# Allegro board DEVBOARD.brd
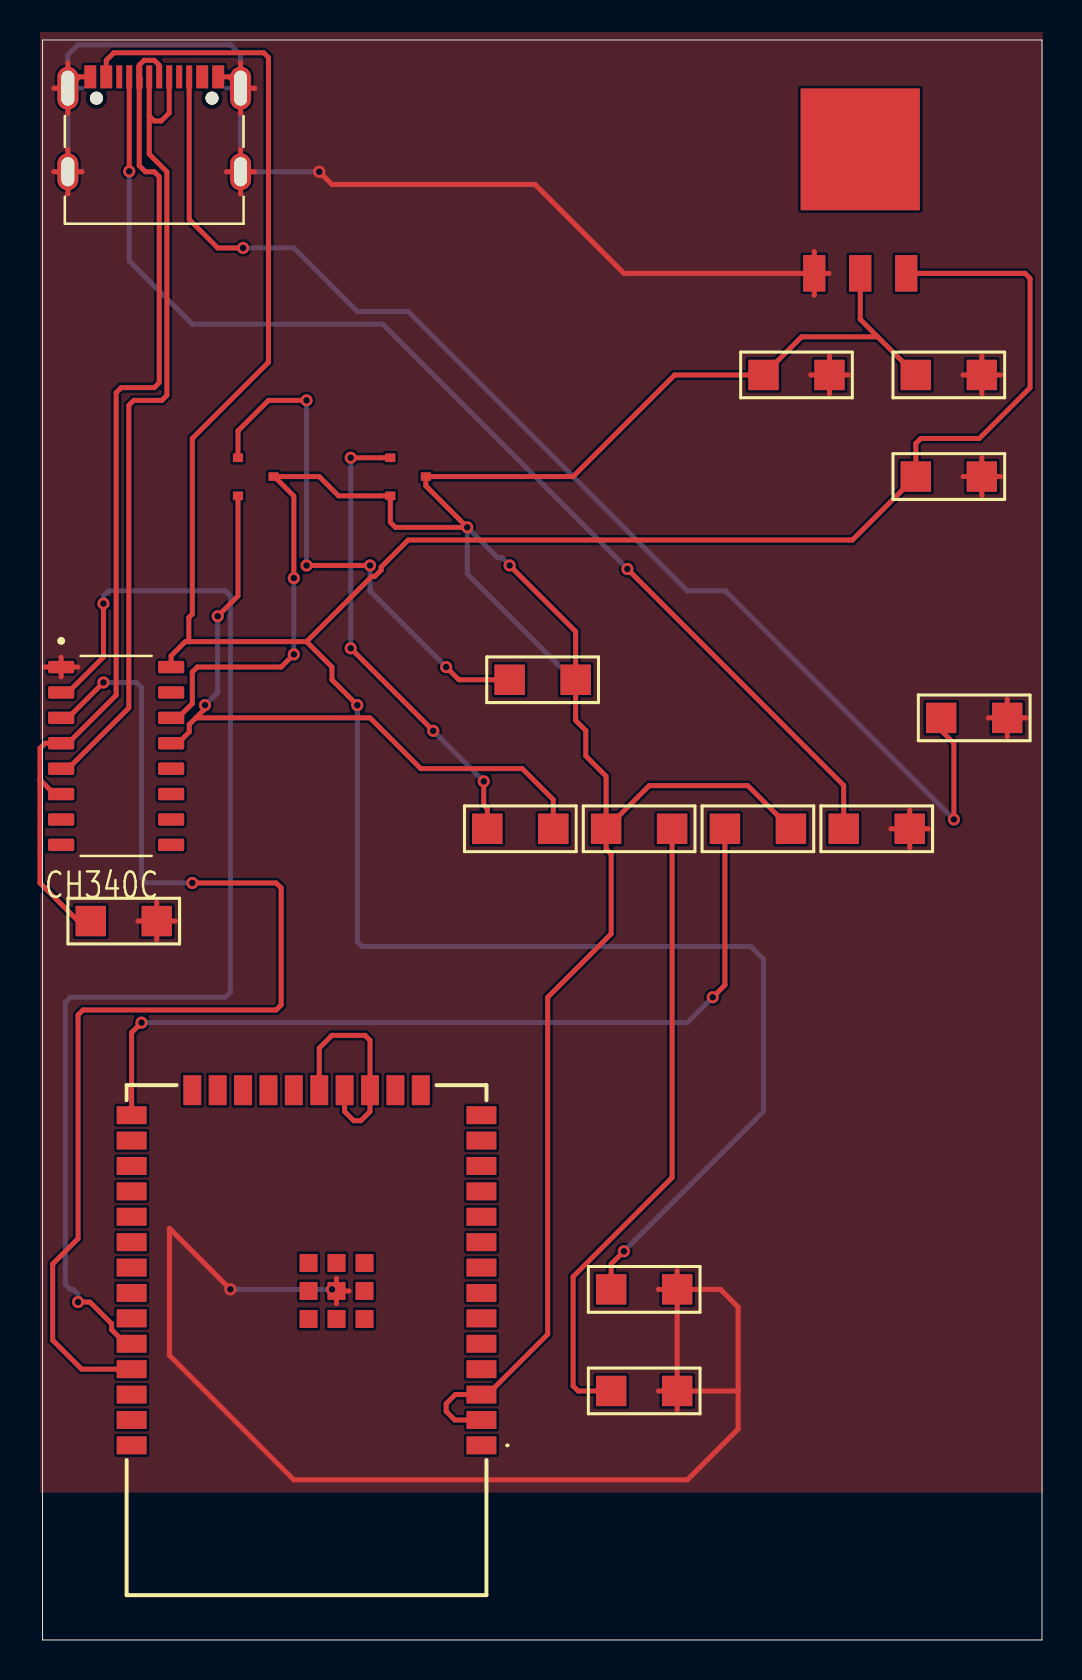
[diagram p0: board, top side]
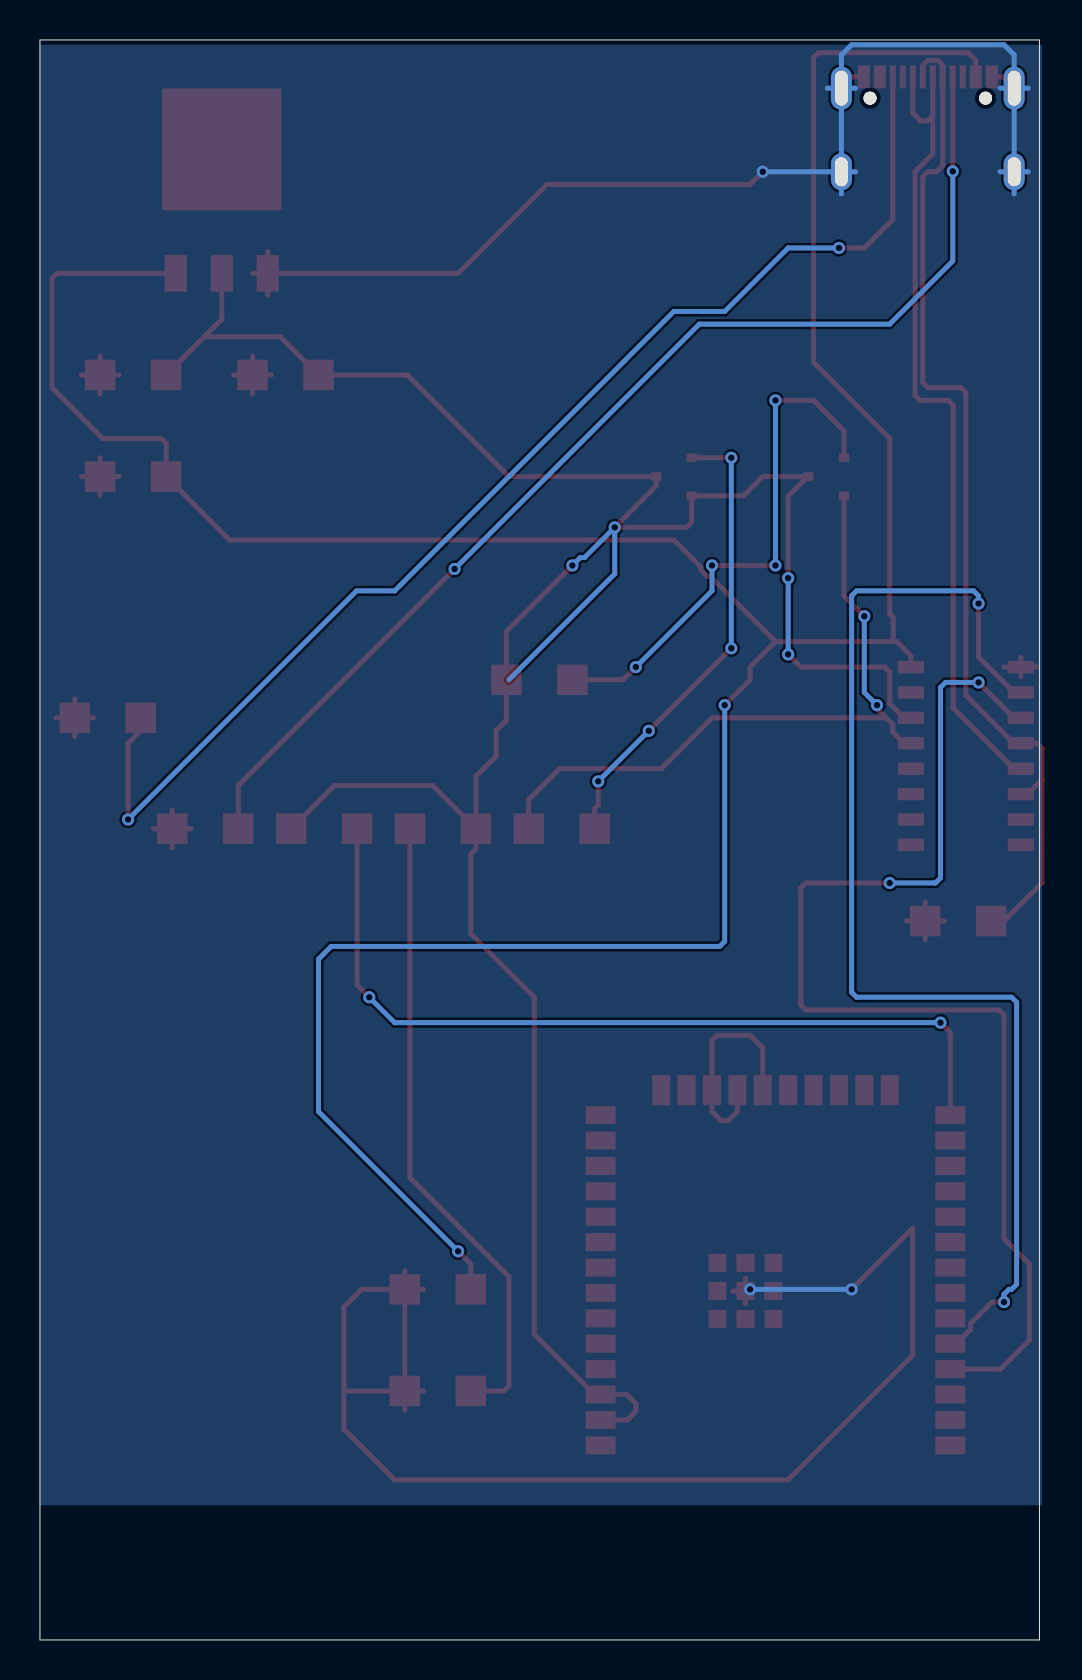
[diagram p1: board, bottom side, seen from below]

Outline 50 x 80 mm; copper layers: TOP, BOTTOM. Coordinates in mm from the lower left corner of the outline.
Outline path: 0,80 50,80 50,0 0,0 0,80

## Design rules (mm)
constraint set DEFAULT: min track width 0.25

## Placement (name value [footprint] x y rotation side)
C3  10u  [SMC1206]  43.69 63.25 0 top
C4  100u  [SMC1206]  36.07 63.25 0 top
C5  100n  [SMC1206]  2.41 35.95 0 top
C6  10u  [SMC1206]  43.69 58.17 0 top
C7  100u  [SMC1206]  28.45 17.53 0 top
C8  1u  [SMC1206]  28.45 12.45 0 top
IC1  ESP32-WROOM-32E-N8  [ESP32WROOM32EN8]  13.21 14.99 180 top
J1  10155435-00011LF  [AMPHENOL_10155435-00031LF]  5.59 73.41 0 top
Q1  NPN  [SOT23]  10.67 58.17 0 top
Q2  NPN  [SOT23]  18.29 58.17 0 top
R1  10k  [SMC1206]  23.37 48.01 0 top
R2  10k  [SMC1206]  22.25 40.56 0 top
R3  5.1k  [SMC1206]  40.08 40.56 0 top
R4  5.1k  [SMC1206]  44.96 46.11 0 top
R5  10k  [SMC1206]  28.19 40.56 0 top
R6  10k  [SMC1206]  34.14 40.56 0 top
U1  AMS1117-33  [AMS1117]  38.61 68.33 0 top
U2  CH340C  [SOIC127P600X180-16N-1]  3.68 44.2 0 top

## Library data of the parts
C3-C7 = CAP
C8 = C
IC1 = ESP32-WROOM-32E-N8
J1 = 10155435-00011LF
Q1 Q2 = NPN
R1-R6 = R
U1 = AMS1117-33
U2 = CH340C

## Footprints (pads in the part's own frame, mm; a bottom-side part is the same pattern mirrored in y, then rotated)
AMPHENOL_10155435-00031LF
  round 0.65 hole 0.65 unplated: (-2.89,3.68) (2.89,3.68)
  rect 0.6x1.15 smd: A1_B12(-3.2,4.745) A4_B9(-2.4,4.745) B1_A12(3.2,4.745) B4_A9(2.4,4.745)
  rect 0.3x1.15 smd: A5(-1.25,4.745) A6(-0.25,4.745) A7(0.25,4.745) A8(1.25,4.745) B5(1.75,4.745) B6(0.75,4.745) B7(-0.75,4.745) B8(-1.75,4.745)
  oval 1.05x2.15 hole 0.65x1.75: SH1(-4.32,4.18) SH2(4.32,4.18)
  oval 1.05x1.85 hole 0.65x1.45: SH3(-4.32,0) SH4(4.32,0)
AMS1117
  rect 1.118x1.829 smd: 1(0,0) 2(2.3,0) 3(4.6,0)
  rect 5.969x6.096 smd: 4(2.3,6.2)
ESP32WROOM32EN8
  rect 1.5x0.9 smd: 1(-8.75,5.26) 2(-8.75,3.99) 3(-8.75,2.72) 4(-8.75,1.45) 5(-8.75,0.18) 6(-8.75,-1.09) 7(-8.75,-2.36) 8(-8.75,-3.63) 9(-8.75,-4.9) 10(-8.75,-6.17) 11(-8.75,-7.44) 12(-8.75,-8.71) 13(-8.75,-9.98) 14(-8.75,-11.25) 25(8.75,-11.25) 26(8.75,-9.98) 27(8.75,-8.71) 28(8.75,-7.44) 29(8.75,-6.17) 30(8.75,-4.9) 31(8.75,-3.63) 32(8.75,-2.36) 33(8.75,-1.09) 34(8.75,0.18) 35(8.75,1.45) 36(8.75,2.72) 37(8.75,3.99) 38(8.75,5.26)
  rect 0.9x1.5 smd: 15(-5.715,-12.5) 16(-4.445,-12.5) 17(-3.175,-12.5) 18(-1.905,-12.5) 19(-0.635,-12.5) 20(0.635,-12.5) 21(1.905,-12.5) 22(3.175,-12.5) 23(4.445,-12.5) 24(5.715,-12.5)
  rect 0.9x0.9 smd: 39(-2.9,-1.06) 40(-2.9,-2.46) 41(-2.9,-3.86) 42(-1.5,-3.86) 43(-0.1,-3.86) 44(-0.1,-2.46) 45(-0.1,-1.06) 46(-1.5,-1.06) 47(-1.5,-2.46)
SMC1206
  rect 1.524x1.524 smd: 1(0,0) 2(3.302,0)
SOIC127P600X180-16N-1
  custom 0.155x0.155 smd: 1(-2.75,4.445) 2(-2.75,3.175) 3(-2.75,1.905) 4(-2.75,0.635) 5(-2.75,-0.635) 6(-2.75,-1.905) 7(-2.75,-3.175) 8(-2.75,-4.445) 9(2.75,-4.445) 10(2.75,-3.175) 11(2.75,-1.905) 12(2.75,-0.635) 13(2.75,0.635) 14(2.75,1.905) 15(2.75,3.175) 16(2.75,4.445)
SOT23
  rect 0.508x0.432 smd: 1(-0.889,0.94) 2(-0.889,-0.965) 3(0.889,0)

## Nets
+3.3V: C3.1 C4.1 IC1.2 IC1.3 Q1.3 Q2.2(E) Q2.3 R1.2 R5.1 R6.2 U1.2(VOUT) U2.14
GND: C3.2 C4.2 C5.2 C6.2 C7.2 C8.2 IC1.47 J1.A1_B12 J1.B1_A12 J1.SH1 J1.SH2 J1.SH3 J1.SH4 R3.2 R4.2 U1.1 U2.1
VBUS: J1.B4_A9(VBUS#B4_A9)
N00220: C6.1 C7.1 J1.A4_B9 U1.3 U2.16(VCC)
N00580: C5.1 J1.A7 J1.B7 U2.4 U2.6
N00651: Q1.1 R1.1
N00688: Q1.2(E) R2.2 U2.13
N00700: Q2.1 R2.1
N02689: J1.A6 J1.B6 U2.5
N03722: J1.B5 R4.1
N03803: J1.A5 R3.1
N05631: IC1.34 U2.2
N05656: IC1.35(TXD0) U2.3
N05861: C8.1 R5.2
N16284: IC1.25 R6.1
N1550016: IC1.17 IC1.18 IC1.19

Pads without a net: IC1 1 4 5 6 7 8 9 10 11 12 13 14 15 16 20 21 22 23 24 26 27 28 29 30 31 32 33 36 37 38 39 40 41 42 43 44 45 46; J1 A8 B8; U1 4; U2 7 8 9 10 11 12 15

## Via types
v1: diameter 0.61, hole 0.33, TOP to BOTTOM, 29 vias

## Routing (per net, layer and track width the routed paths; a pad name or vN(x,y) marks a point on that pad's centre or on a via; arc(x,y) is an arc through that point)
+3.3V: length 138.8
  TOP w0.25: 11.59,58.17 11.56,58.17 ; 11.59,58.17 12.57,57.19 v1(12.57,53.09) ; 11.59,58.17 13.84,58.17 14.81,57.21 17.4,57.21 17.4,55.89 17.65,55.63 v1(21.25,55.63) 19.18,57.7 Q2.3 26.54,58.17 31.62,63.25 C4.1 37.97,65.16 41.78,65.16 ; 41.78,65.16 40.91,66.03 U1.2 ; 41.78,65.16 C3.1 ; R5.1 28.19,43.19 27.18,44.2 27.18,45.47 26.67,45.98 R1.2 26.67,50.42 v1(23.37,53.73) ; R5.1 30.35,42.72 35.28,42.72 R6.2 ; R5.1 28.19,39.55 28.45,39.29 28.45,35.31 25.27,32.14 25.27,15.29 22.26,12.27 IC1.3 20.65,12.27 20.19,11.82 20.19,11.43 20.62,11 IC1.2 ; v1(12.57,49.28) 11.94,48.65 7.74,48.65 7.49,48.4 7.49,46.82 6.78,46.11 U2.14
  BOTTOM w0.25: v1(23.37,53.73) 22.97,54.12 22.76,54.12 v1(21.25,55.63) 21.25,53.31 26.54,48.01 ; v1(12.57,49.28) v1(12.57,53.09)
GND: length 174.5
  TOP w0.25: 0.1,48.65 U2.1 ; U2.1 0.93,48.16 ; U2.1 1.76,48.65 ; U2.1 0.93,49.13 ; 42.44,40.56 R3.2 ; R3.2 44.32,40.56 ; R3.2 43.38,41.5 ; R3.2 43.38,39.62 ; 46.99,62.31 C3.2 ; C3.2 46.99,64.19 ; C3.2 47.93,63.25 ; C3.2 46.05,63.25 ; R4.2 49.2,46.11 ; R4.2 48.26,47.05 ; R4.2 48.26,45.17 ; R4.2 47.32,46.11 ; U1.1 29.08,68.33 24.64,72.78 14.48,72.78 v1(13.84,73.41) ; U1.1 39.34,68.33 ; U1.1 38.61,69.42 ; U1.1 38.61,67.24 ; C7.2 C8.2 ; C7.2 30.81,17.53 ; C7.2 33.91,17.53 34.8,16.65 34.8,12.45 ; C7.2 31.75,18.47 ; C8.2 30.81,12.45 ; C8.2 34.8,12.45 ; C8.2 31.75,11.51 ; J1.SH4 10.61,73.41 ; J1.SH4 9.91,74.51 ; J1.SH4 9.2,73.41 ; J1.SH4 9.91,72.31 ; C5.2 6.65,35.95 ; C5.2 5.71,36.89 ; C5.2 4.77,35.95 ; C5.2 5.71,35.01 ; J1.SH2 9.91,78.84 ; J1.SH2 9.34,78.16 8.79,78.16 ; J1.SH2 9.91,76.34 ; J1.SH2 10.61,77.59 ; 46.99,57.23 C6.2 ; C6.2 46.99,59.11 ; C6.2 46.05,58.17 ; C6.2 47.93,58.17 ; IC1.47 14.71,18.08 ; IC1.47 15.33,17.45 ; IC1.47 14.71,16.82 ; IC1.47 14.63,17.53 v1(14.48,17.53) ; 39.37,62.31 C4.2 ; C4.2 38.43,63.25 ; C4.2 39.37,64.19 ; C4.2 40.31,63.25 ; 34.8,12.45 34.8,10.55 32.26,8.01 12.57,8.01 6.35,14.23 6.35,20.58 v1(9.4,17.53) ; 1.27,72.31 J1.SH3 ; J1.SH3 1.27,74.51 ; J1.SH3 1.97,73.41 ; J1.SH3 0.56,73.41 ; J1.SH1 1.83,78.16 2.39,78.16 ; J1.SH1 1.27,78.84 ; J1.SH1 0.56,77.59 ; J1.SH1 1.27,76.34
  BOTTOM w0.25: 0.56,73.41 J1.SH3 ; J1.SH3 1.97,73.41 ; J1.SH3 1.27,72.31 ; J1.SH3 J1.SH1 ; v1(13.84,73.41) J1.SH4 ; J1.SH4 9.2,73.41 ; J1.SH4 J1.SH2 ; J1.SH4 9.91,72.31 ; J1.SH1 1.97,77.59 ; J1.SH1 1.27,79.25 1.78,79.76 9.4,79.76 9.91,79.25 J1.SH2 ; J1.SH1 0.56,77.59 ; 9.2,77.59 J1.SH2 ; J1.SH2 10.61,77.59 ; v1(9.4,17.53) v1(14.48,17.53)
N00220: length 158.4
  TOP w0.25: 7.32,49.92 13.21,49.92 ; 7.32,49.92 7.32,51.12 7.49,51.3 7.49,60.08 11.3,63.89 11.3,79.13 11.07,79.36 3.56,79.36 3.19,78.98 3.19,78.16 ; 7.32,49.92 7.14,49.92 6.43,49.21 U2.16 ; 13.21,49.92 16.46,53.17 16.61,53.17 16.94,53.5 16.94,53.65 18.29,55 40.51,55 C6.1 43.69,59.83 43.94,60.08 46.86,60.08 49.4,62.62 49.4,68.08 49.15,68.33 U1.3 ; 13.21,49.92 14.48,48.65 14.48,48.01 v1(15.75,46.74) ; C7.1 28.45,18.8 v1(29.08,19.44)
  BOTTOM w0.25: v1(15.75,46.74) 15.75,34.93 16,34.68 35.43,34.68 36.07,34.04 36.07,26.42 v1(29.08,19.44)
N00580: length 52.2
  TOP w0.25: -0.13,43.01 0.59,42.3 U2.6 ; -0.13,43.01 -0.13,44.59 0.12,44.84 1.28,44.84 3.68,47.24 3.68,62.37 3.93,62.62 5.59,62.62 5.84,62.87 5.84,73.16 5.59,73.41 5.14,73.41 4.84,73.72 4.84,77.59 4.87,77.63 4.87,78.09 4.84,78.12 4.84,78.74 5.08,78.98 5.59,78.98 5.84,78.74 5.84,78.16 ; -0.13,43.01 -0.13,37.85 1.78,35.95 C5.1
N00651: length 26.9
  TOP w0.25: Q1.1 9.78,60.46 11.3,61.98 v1(13.21,61.98) ; R1.1 20.83,48.01 v1(20.19,48.65) ; v1(13.21,53.73) v1(16.38,53.73)
  BOTTOM w0.25: v1(16.38,53.73) 16.38,52.46 v1(20.19,48.65) ; v1(13.21,61.98) v1(13.21,53.73)
N00688: length 35
  TOP w0.25: 7.67,46.11 16.38,46.11 18.92,43.57 24,43.57 25.55,42.02 R2.2 ; 7.67,46.11 8.13,46.56 v1(8.13,46.74) ; 7.67,46.11 7.34,45.77 7.34,45.4 6.78,44.84 6.43,44.84 ; v1(8.76,51.19) 9.78,52.2 Q1.2
  BOTTOM w0.25: v1(8.76,51.19) 8.76,47.38 v1(8.13,46.74)
N00700: length 23.4
  TOP w0.25: v1(22.07,42.93) 22.07,41.75 22.25,41.57 R2.1 ; 17.4,59.11 v1(15.42,59.11) ; v1(15.42,49.59) v1(19.54,45.46)
  BOTTOM w0.25: v1(15.42,59.11) v1(15.42,49.59) ; v1(19.54,45.46) v1(22.07,42.93)
N02689: length 41.2
  TOP w0.25: 5.34,76.2 5.34,78.16 ; 5.34,76.2 5.34,74.3 6.22,73.41 6.22,62.23 5.97,61.98 4.57,61.98 4.32,61.73 4.32,46.61 1.28,43.57 U2.5 ; 5.34,76.2 5.59,75.95 5.94,75.95 6.34,76.35 6.34,78.16
N03722: length 63.2
  TOP w0.25: 7.34,78.16 7.34,71.03 8.76,69.6 v1(10.03,69.6) ; R4.1 44.96,45.47 45.59,44.84 v1(45.59,41.03)
  BOTTOM w0.25: v1(10.03,69.6) 12.57,69.6 15.75,66.43 18.29,66.43 32.26,52.46 34.16,52.46 v1(45.59,41.03)
N03803: length 58
  TOP w0.25: v1(29.26,53.55) 40.08,42.73 R3.1 ; 4.34,78.16 v1(4.34,73.43)
  BOTTOM w0.25: v1(4.34,73.43) 4.34,68.95 7.49,65.79 17.02,65.79 v1(29.26,53.55)
N05631: length 59.8
  TOP w0.25: IC1.34 4.16,14.81 3.45,15.51 3.45,15.81 2.37,16.9 v1(1.78,16.9) ; U2.2 1.28,47.38 3.05,49.15 v1(3.05,51.82)
  BOTTOM w0.25: v1(3.05,51.82) 3.05,52.21 3.3,52.46 9.15,52.46 9.4,52.21 9.4,32.39 9.15,32.14 1.39,32.14 1.14,31.89 1.14,17.78 1.39,17.53 1.53,17.53 1.78,17.28 v1(1.78,16.9)
N05656: length 59.1
  TOP w0.25: U2.3 1.28,46.11 v1(3.05,47.88) ; IC1.35 1.96,13.54 0.51,14.99 0.51,18.8 1.78,20.07 1.78,31.25 2.03,31.5 11.69,31.5 11.94,31.75 11.94,37.6 11.69,37.85 v1(7.49,37.85)
  BOTTOM w0.25: v1(7.49,37.85) 5.2,37.85 4.95,38.1 4.95,47.63 4.7,47.88 v1(3.05,47.88)
N05861: length 31.9
  TOP w0.25: R5.2 31.49,23.12 26.54,18.17 26.54,12.7 26.79,12.45 C8.1
N16284: length 42.6
  TOP w0.25: R6.1 34.14,32.75 v1(33.53,32.14) ; v1(4.95,30.87) 4.46,30.37 IC1.25
  BOTTOM w0.25: v1(33.53,32.14) 32.26,30.87 v1(4.95,30.87)
N1550016: length 11.3
  TOP w0.25: IC1.19 13.84,29.6 14.48,30.23 16.13,30.23 16.38,29.98 IC1.17 16.38,26.42 15.92,25.96 15.57,25.96 15.11,26.42 IC1.18

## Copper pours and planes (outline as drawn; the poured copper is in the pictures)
GND on TOP: -0.13,80.4 -0.13,7.37 50.04,7.37 50.04,80.4
GND on BOTTOM: -0.13,79.76 -0.13,6.74 50.04,6.74 50.04,79.76
